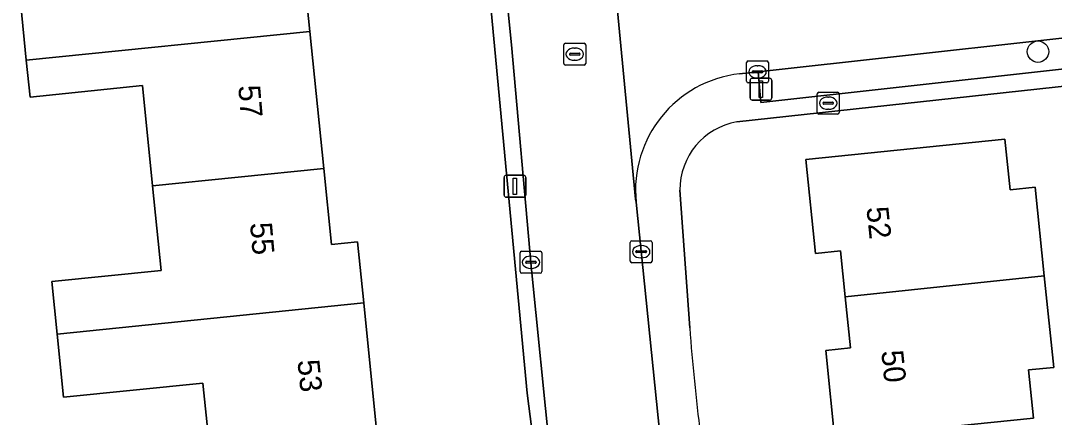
# Model space of a CAD drawing. Extents: x 158455 to 159797, y 387218 to 388672.
# Drawn here: x 159054.2 to 159101.4, y 387882.52 to 387900.61 of the extents above; entities that cross this region are included whole.
import ezdxf

# ---------------------------------------------------------------- set-up
doc = ezdxf.new("R2010")
doc.units = 0
for name, color, linetype in [('IMGEO_Boom', 7, 'Continuous'), ('IMGEO_Brandkraan', 7, 'Continuous'), ('IMGEO_Erf', 7, 'Continuous'), ('IMGEO_Kolk', 7, 'Continuous'), ('IMGEO_Lichtmast', 7, 'Continuous'), ('IMGEO_Pand', 7, 'Continuous'), ('IMGEO_Pand_nummerreeks', 7, 'Continuous'), ('IMGEO_Parkeervlak_open', 7, 'Continuous'), ('IMGEO_Rijbaan_lokaal_open', 7, 'Continuous'), ('IMGEO_Rioolput', 7, 'Continuous'), ('IMGEO_Voetpad_open', 7, 'Continuous')]:
    doc.layers.add(name, color=color, linetype=linetype)

msp = doc.modelspace()

# ---------------------------------------------------------------- linework, layer by layer
at = {"layer": 'IMGEO_Boom'}
msp.add_circle((159100.657, 387899.195), 0.489, dxfattribs=at)
at = {"layer": 'IMGEO_Brandkraan'}
for p, q in [((159090.578, 387896.42), (159090.578, 387897.272)), ((159090.653, 387897.346), (159091.505, 387897.346)), ((159091.066, 387897.126), (159091.091, 387897.126)), ((159091.579, 387897.272), (159091.579, 387896.42)), ((159090.837, 387896.84), (159090.837, 387896.852)), ((159091.275, 387896.803), (159090.877, 387896.803)), ((159090.88, 387896.889), (159091.278, 387896.889)), ((159091.089, 387896.566), (159091.064, 387896.566)), ((159091.321, 387896.852), (159091.321, 387896.84)), ((159091.505, 387896.346), (159090.653, 387896.346))]:
    msp.add_line(p, q, dxfattribs=at)
for points in [[(159090.578, 387896.42), (159090.578, 387897.272)], [(159090.653, 387897.346), (159091.505, 387897.346)], [(159091.579, 387897.272), (159091.579, 387896.42)], [(159091.505, 387896.346), (159090.653, 387896.346)]]:
    msp.add_lwpolyline(points, dxfattribs=at)
for centre, radius, start, end in [((159090.655, 387897.27), 0.0765, 91.552, 178.448), ((159090.655, 387897.27), 0.0765, 91.552, 178.448), ((159091.503, 387897.27), 0.0765, 1.552, 88.448), ((159091.503, 387897.27), 0.0765, 1.552, 88.448), ((159090.877, 387896.849), 0.0403, 85.8775, 175.7526), ((159090.874, 387896.839), 0.0366, 178.938, 274.7102), ((159091.278, 387896.846), 0.043, 264.8664, 352.4533), ((159091.282, 387896.851), 0.0386, 1.7309, 96.639), ((159090.655, 387896.422), 0.0765, 181.552, 268.448), ((159090.655, 387896.422), 0.0765, 181.552, 268.448), ((159091.503, 387896.422), 0.0765, 271.552, 358.448), ((159091.503, 387896.422), 0.0765, 271.552, 358.448)]:
    msp.add_arc(centre, radius, start, end, dxfattribs=at)
for centre, major_axis, ratio, start_param, end_param in [((159091.065, 387896.846), (-0.387, 0.002), 0.722429, 4.712389, 7.853982), ((159091.09, 387896.846), (-0.39, 0.002), 0.717154, 1.570796, 4.712389)]:
    msp.add_ellipse(centre, major_axis=major_axis, ratio=ratio, start_param=start_param, end_param=end_param, dxfattribs=at)
at = {"layer": 'IMGEO_Erf'}
for points in [[(159066.771, 387906.369), (159067.406, 387900.119), (159068.041, 387893.868), (159068.394, 387890.398), (159069.587, 387890.519), (159069.87, 387887.739), (159070.505, 387881.488)], [(159062.868, 387880.711), (159062.526, 387884.08), (159056.166, 387883.433), (159055.873, 387886.314), (159055.629, 387888.711), (159060.623, 387889.219), (159060.231, 387893.073), (159059.766, 387897.647), (159054.63, 387897.125), (159054.459, 387898.8), (159054.204, 387901.31)], [(159078.911, 387872.765), (159078.029, 387878.175), (159077.339, 387883.613), (159075.691, 387901.078)], [(159112.244, 387883.827), (159108.986, 387883.456), (159108.764, 387885.763), (159106.356, 387885.52), (159105.956, 387889.484), (159105.553, 387893.485), (159107.961, 387893.728), (159107.575, 387898.138), (159102.974, 387897.735), (159086.912, 387895.992)], [(159101.899, 387853.4), (159099.017, 387858.943), (159096.134, 387864.486), (159093.252, 387870.03), (159090.315, 387875.678), (159093.433, 387877.3), (159091.415, 387881.181), (159090.963, 387885.565), (159092.093, 387885.681), (159091.852, 387888.018), (159091.637, 387890.109), (159090.5, 387889.992), (159090.059, 387894.269), (159099.141, 387895.206), (159099.38, 387892.891), (159100.528, 387893.009), (159100.945, 387888.963), (159101.375, 387884.793), (159100.224, 387884.675), (159100.451, 387882.478), (159095.806, 387881.999), (159100.162, 387873.622), (159101.79, 387870.492)], [(159084.309, 387892.873), (159084.758, 387886.59)]]:
    msp.add_lwpolyline(points, dxfattribs=at)
for centre, radius, start, end in [((159087.44, 387892.906), 3.131, 99.705, 180.6008), ((159165.101, 387892.253), 80.542, 184.03216, 190.9386)]:
    msp.add_arc(centre, radius, start, end, dxfattribs=at)
at = {"layer": 'IMGEO_Kolk'}
for p, q in [((159087.349, 387897.847), (159087.349, 387898.699)), ((159087.424, 387898.773), (159088.276, 387898.773)), ((159087.837, 387898.553), (159087.862, 387898.553)), ((159088.35, 387898.699), (159088.35, 387897.847)), ((159087.608, 387898.267), (159087.608, 387898.279)), ((159088.046, 387898.23), (159087.648, 387898.23)), ((159087.651, 387898.316), (159088.049, 387898.316)), ((159087.86, 387897.993), (159087.835, 387897.993)), ((159088.092, 387898.279), (159088.092, 387898.267)), ((159088.276, 387897.773), (159087.424, 387897.773)), ((159082.037, 387889.643), (159082.037, 387890.495)), ((159082.112, 387890.569), (159082.964, 387890.569)), ((159083.038, 387890.495), (159083.038, 387889.643)), ((159077.005, 387889.162), (159077.005, 387890.014)), ((159077.08, 387890.088), (159077.932, 387890.088)), ((159078.006, 387890.014), (159078.006, 387889.162)), ((159082.296, 387890.063), (159082.296, 387890.075)), ((159082.734, 387890.026), (159082.336, 387890.026)), ((159082.339, 387890.112), (159082.737, 387890.112)), ((159082.525, 387890.349), (159082.55, 387890.349)), ((159082.78, 387890.075), (159082.78, 387890.063)), ((159077.264, 387889.582), (159077.264, 387889.594)), ((159077.702, 387889.545), (159077.304, 387889.545)), ((159077.307, 387889.631), (159077.705, 387889.631)), ((159077.493, 387889.868), (159077.518, 387889.868)), ((159077.748, 387889.594), (159077.748, 387889.582)), ((159082.964, 387889.569), (159082.112, 387889.569)), ((159082.548, 387889.789), (159082.523, 387889.789)), ((159077.932, 387889.088), (159077.08, 387889.088)), ((159077.516, 387889.308), (159077.491, 387889.308))]:
    msp.add_line(p, q, dxfattribs=at)
for points in [[(159087.349, 387897.847), (159087.349, 387898.699)], [(159087.424, 387898.773), (159088.276, 387898.773)], [(159088.35, 387898.699), (159088.35, 387897.847)], [(159088.276, 387897.773), (159087.424, 387897.773)], [(159082.037, 387889.643), (159082.037, 387890.495)], [(159082.112, 387890.569), (159082.964, 387890.569)], [(159083.038, 387890.495), (159083.038, 387889.643)], [(159077.005, 387889.162), (159077.005, 387890.014)], [(159077.08, 387890.088), (159077.932, 387890.088)], [(159078.006, 387890.014), (159078.006, 387889.162)], [(159082.964, 387889.569), (159082.112, 387889.569)], [(159077.932, 387889.088), (159077.08, 387889.088)]]:
    msp.add_lwpolyline(points, dxfattribs=at)
for centre, radius, start, end in [((159087.426, 387898.697), 0.0765, 91.552, 178.448), ((159087.426, 387898.697), 0.0765, 91.552, 178.448), ((159088.274, 387898.697), 0.0765, 1.552, 88.448), ((159088.274, 387898.697), 0.0765, 1.552, 88.448), ((159087.648, 387898.276), 0.0403, 85.8775, 175.7526), ((159087.645, 387898.266), 0.0366, 178.938, 274.7102), ((159088.049, 387898.273), 0.043, 264.8664, 352.4533), ((159088.053, 387898.278), 0.0386, 1.7309, 96.639), ((159087.426, 387897.849), 0.0765, 181.552, 268.448), ((159087.426, 387897.849), 0.0765, 181.552, 268.448), ((159088.274, 387897.849), 0.0765, 271.552, 358.448), ((159088.274, 387897.849), 0.0765, 271.552, 358.448), ((159082.114, 387890.493), 0.0765, 91.552, 178.448), ((159082.114, 387890.493), 0.0765, 91.552, 178.448), ((159082.962, 387890.493), 0.0765, 1.552, 88.448), ((159082.962, 387890.493), 0.0765, 1.552, 88.448), ((159077.082, 387890.012), 0.0765, 91.552, 178.448), ((159077.082, 387890.012), 0.0765, 91.552, 178.448), ((159077.93, 387890.012), 0.0765, 1.552, 88.448), ((159077.93, 387890.012), 0.0765, 1.552, 88.448), ((159082.336, 387890.072), 0.0403, 85.8775, 175.7526), ((159082.333, 387890.062), 0.0366, 178.938, 274.7102), ((159082.737, 387890.069), 0.043, 264.8664, 352.4533), ((159082.741, 387890.074), 0.0386, 1.7309, 96.639), ((159077.304, 387889.591), 0.0403, 85.8775, 175.7526), ((159077.301, 387889.581), 0.0366, 178.938, 274.7102), ((159077.705, 387889.588), 0.043, 264.8664, 352.4533), ((159077.709, 387889.593), 0.0386, 1.7309, 96.639), ((159082.114, 387889.645), 0.0765, 181.552, 268.448), ((159082.114, 387889.645), 0.0765, 181.552, 268.448), ((159082.962, 387889.645), 0.0765, 271.552, 358.448), ((159082.962, 387889.645), 0.0765, 271.552, 358.448), ((159077.082, 387889.164), 0.0765, 181.552, 268.448), ((159077.082, 387889.164), 0.0765, 181.552, 268.448), ((159077.93, 387889.164), 0.0765, 271.552, 358.448), ((159077.93, 387889.164), 0.0765, 271.552, 358.448)]:
    msp.add_arc(centre, radius, start, end, dxfattribs=at)
for centre, major_axis, ratio, start_param, end_param in [((159087.836, 387898.273), (-0.387, 0.002), 0.722429, 4.712389, 7.853982), ((159087.861, 387898.273), (-0.39, 0.002), 0.717154, 1.570796, 4.712389), ((159082.524, 387890.069), (-0.387, 0.002), 0.722429, 4.712389, 7.853982), ((159082.549, 387890.069), (-0.39, 0.002), 0.717154, 1.570796, 4.712389), ((159077.492, 387889.588), (-0.387, 0.002), 0.722429, 4.712389, 7.853982), ((159077.517, 387889.588), (-0.39, 0.002), 0.717154, 1.570796, 4.712389)]:
    msp.add_ellipse(centre, major_axis=major_axis, ratio=ratio, start_param=start_param, end_param=end_param, dxfattribs=at)
at = {"layer": 'IMGEO_Lichtmast'}
for p, q in [((159087.61, 387897.984), (159088.4, 387897.984)), ((159088.4, 387897.984), (159087.61, 387897.984)), ((159087.51, 387897.084), (159087.51, 387897.884)), ((159087.51, 387897.884), (159087.51, 387897.084)), ((159088.5, 387897.884), (159088.5, 387897.084)), ((159088.5, 387897.084), (159088.5, 387897.884)), ((159088.4, 387896.984), (159087.61, 387896.984)), ((159087.61, 387896.984), (159088.4, 387896.984)), ((159076.276, 387892.655), (159076.276, 387893.455)), ((159076.276, 387893.455), (159076.276, 387892.655)), ((159076.376, 387893.555), (159077.166, 387893.555)), ((159077.166, 387893.555), (159076.376, 387893.555)), ((159077.266, 387893.455), (159077.266, 387892.655)), ((159077.266, 387892.655), (159077.266, 387893.455)), ((159077.166, 387892.555), (159076.376, 387892.555)), ((159076.376, 387892.555), (159077.166, 387892.555))]:
    msp.add_line(p, q, dxfattribs=at)
for points in [[(159087.93, 387897.859), (159088.08, 387897.859), (159088.08, 387897.109), (159087.93, 387897.109), (159087.93, 387897.859)], [(159076.696, 387893.43), (159076.846, 387893.43), (159076.846, 387892.68), (159076.696, 387892.68), (159076.696, 387893.43)]]:
    msp.add_lwpolyline(points, dxfattribs=at)
for centre, start, end in [((159087.61, 387897.884), 90, 180), ((159087.61, 387897.884), 90, 180), ((159088.4, 387897.884), 0, 90), ((159088.4, 387897.884), 360, 90), ((159087.61, 387897.084), 180, 270), ((159087.61, 387897.084), 180, 270), ((159088.4, 387897.084), 270, 0), ((159088.4, 387897.084), 270, 0), ((159076.376, 387893.455), 90, 180), ((159076.376, 387893.455), 90, 180), ((159077.166, 387893.455), 0, 90), ((159077.166, 387893.455), 360, 90), ((159076.376, 387892.655), 180, 270), ((159076.376, 387892.655), 180, 270), ((159077.166, 387892.655), 270, 0), ((159077.166, 387892.655), 270, 0)]:
    msp.add_arc(centre, 0.1, start, end, dxfattribs=at)
at = {"layer": 'IMGEO_Pand'}
for points in [[(159058.955, 387905.574), (159059.336, 387901.832), (159054.204, 387901.31), (159054.459, 387898.8), (159067.406, 387900.119), (159066.771, 387906.369)], [(159060.231, 387893.073), (159068.041, 387893.868), (159067.406, 387900.119), (159054.459, 387898.8), (159054.63, 387897.125), (159059.766, 387897.647)], [(159091.852, 387888.018), (159100.945, 387888.963), (159100.528, 387893.009), (159099.38, 387892.891), (159099.141, 387895.206), (159090.059, 387894.269), (159090.5, 387889.992), (159091.637, 387890.109)], [(159069.87, 387887.739), (159069.587, 387890.519), (159068.394, 387890.398), (159068.041, 387893.868), (159060.231, 387893.073), (159060.623, 387889.219), (159055.629, 387888.711), (159055.873, 387886.314)], [(159091.852, 387888.018), (159092.093, 387885.681), (159090.963, 387885.565), (159091.415, 387881.181), (159095.806, 387881.999), (159100.451, 387882.478), (159100.224, 387884.675), (159101.375, 387884.793), (159100.945, 387888.963)], [(159069.87, 387887.739), (159055.873, 387886.314), (159056.166, 387883.433), (159062.526, 387884.08), (159062.868, 387880.711), (159070.505, 387881.488)]]:
    msp.add_lwpolyline(points, close=True, dxfattribs=at)
at = {"layer": 'IMGEO_Parkeervlak_open'}
msp.add_lwpolyline([(159087.878, 387898.276), (159088.002, 387896.872), (159107.495, 387899.029), (159107.372, 387900.433)], close=True, dxfattribs=at)
at = {"layer": 'IMGEO_Rijbaan_lokaal_open'}
for points in [[(159078.804, 387928.403), (159073.823, 387927.922), (159073.857, 387927.559), (159074.77, 387918.283), (159076.455, 387901.166), (159076.619, 387899.503), (159077.52, 387889.414), (159078.387, 387880.81)], [(159083.466, 387881.003), (159082.308, 387892.331), (159082.286, 387892.469), (159080.85, 387907.422), (159080.838, 387907.748), (159078.804, 387928.403)], [(159080.838, 387907.748), (159080.85, 387907.422), (159082.286, 387892.469), (159082.308, 387892.331)], [(159087.033, 387898.182), (159087.878, 387898.276), (159107.372, 387900.433)]]:
    msp.add_lwpolyline(points, dxfattribs=at)
msp.add_arc((159087.621, 387892.874), 5.341, 96.3242, 185.8303, dxfattribs=at)
at = {"layer": 'IMGEO_Rioolput'}
for p, q in [((159079.003, 387898.655), (159079.003, 387899.507)), ((159079.078, 387899.581), (159079.93, 387899.581)), ((159079.491, 387899.361), (159079.516, 387899.361)), ((159080.004, 387899.507), (159080.004, 387898.655)), ((159079.262, 387899.075), (159079.262, 387899.087)), ((159079.7, 387899.038), (159079.302, 387899.038)), ((159079.305, 387899.124), (159079.703, 387899.124)), ((159079.746, 387899.087), (159079.746, 387899.075)), ((159079.93, 387898.581), (159079.078, 387898.581)), ((159079.514, 387898.801), (159079.489, 387898.801))]:
    msp.add_line(p, q, dxfattribs=at)
for points in [[(159079.003, 387898.655), (159079.003, 387899.507)], [(159079.078, 387899.581), (159079.93, 387899.581)], [(159080.004, 387899.507), (159080.004, 387898.655)], [(159079.93, 387898.581), (159079.078, 387898.581)]]:
    msp.add_lwpolyline(points, dxfattribs=at)
for centre, radius, start, end in [((159079.08, 387899.505), 0.0765, 91.552, 178.448), ((159079.08, 387899.505), 0.0765, 91.552, 178.448), ((159079.928, 387899.505), 0.0765, 1.552, 88.448), ((159079.928, 387899.505), 0.0765, 1.552, 88.448), ((159079.302, 387899.084), 0.0403, 85.8775, 175.7526), ((159079.299, 387899.074), 0.0366, 178.938, 274.7102), ((159079.703, 387899.081), 0.043, 264.8664, 352.4533), ((159079.707, 387899.086), 0.0386, 1.7309, 96.639), ((159079.08, 387898.657), 0.0765, 181.552, 268.448), ((159079.08, 387898.657), 0.0765, 181.552, 268.448), ((159079.928, 387898.657), 0.0765, 271.552, 358.448), ((159079.928, 387898.657), 0.0765, 271.552, 358.448)]:
    msp.add_arc(centre, radius, start, end, dxfattribs=at)
for centre, major_axis, ratio, start_param, end_param in [((159079.49, 387899.081), (-0.387, 0.002), 0.722429, 4.712389, 7.853982), ((159079.515, 387899.081), (-0.39, 0.002), 0.717154, 1.570796, 4.712389)]:
    msp.add_ellipse(centre, major_axis=major_axis, ratio=ratio, start_param=start_param, end_param=end_param, dxfattribs=at)
at = {"layer": 'IMGEO_Voetpad_open'}
for points in [[(159078.387, 387880.81), (159077.52, 387889.414), (159076.619, 387899.503), (159076.455, 387901.166), (159075.691, 387901.078), (159077.339, 387883.613), (159078.029, 387878.175), (159078.911, 387872.765)], [(159086.912, 387895.992), (159102.974, 387897.735), (159107.575, 387898.138), (159107.495, 387899.029), (159088.002, 387896.872), (159087.878, 387898.276), (159087.033, 387898.182)], [(159084.758, 387886.59), (159084.309, 387892.873)], [(159082.308, 387892.331), (159083.466, 387881.003)]]:
    msp.add_lwpolyline(points, dxfattribs=at)
for centre, radius, start, end in [((159087.621, 387892.874), 5.341, 96.3242, 185.8303), ((159087.44, 387892.906), 3.131, 99.705, 180.6008), ((159165.101, 387892.253), 80.542, 184.03216, 190.9386)]:
    msp.add_arc(centre, radius, start, end, dxfattribs=at)

# ---------------------------------------------------------------- texts
at = {"layer": 'IMGEO_Pand_nummerreeks'}
for s, rotation, p in [('57', 274.9352, (159064.135, 387897.63)), ('52', 275.9151, (159092.82, 387892.082)), ('55', 274.9352, (159064.676, 387891.37)), ('50', 275.9151, (159093.499, 387885.532)), ('53', 275.8095, (159066.839, 387885.104))]:
    msp.add_text(s, height=1, rotation=rotation, dxfattribs=at).set_placement(p)

doc.saveas('drawing.dxf')
